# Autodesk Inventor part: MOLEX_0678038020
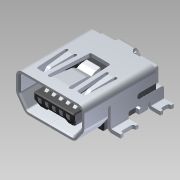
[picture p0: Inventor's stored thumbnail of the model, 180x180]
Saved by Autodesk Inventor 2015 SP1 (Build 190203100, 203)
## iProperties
Created: 2015-05
Part Number: MOLEX_0678038020
Material: Generic
Document SubType Name: Modeling
Designer: kazys
Density: 1 g/cm^3
Appearance: Default
Author: kazys
Title: MOLEX_0678038020.STEP
Description: STEP AP214
Creation Date: 2015-04-13
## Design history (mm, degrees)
node "MOLEX_06780380201"
node "Sketched Bend27"
node "Cut-Extrude4"
node "Cut-Extrude5"
node "Base1"
node "Base2"
node "Base3"
